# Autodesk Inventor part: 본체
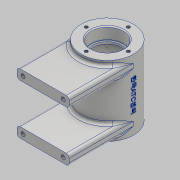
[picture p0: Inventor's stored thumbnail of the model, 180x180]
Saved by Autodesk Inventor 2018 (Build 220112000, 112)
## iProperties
Created: 2020-07
Part Number: 본체
Material: 알루미늄 6061
Document SubType Name: Modeling
Designer: home
Density: 2.7 g/cm^3
Appearance: 알루미늄 - 평지
Mass: 305.265 g
Surface Area: 357.573 cm^2
Volume: 113.061 cm^3
Author: home
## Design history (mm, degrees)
sketch "스케치1"
  geometry: L1 (0, 0)-(0, -55.603); L2 (26, 7.199)-(17, 7.199); L3 (16, 6.199)-(16, -4.501); L4 (15.7, -4.801)-(14, -4.801); L5 (14, -4.801)-(14, -6.801); L6 (14, -6.801)-(18, -6.801); L7 (21, -9.801)-(21, -45.801); L8 (18, -48.801)-(14, -48.801); L9 (14, -48.801)-(14, -50.801); L10 (14, -50.801)-(15.7, -50.801); L11 (16, -51.101)-(16, -61.801); L12 (17, -62.801)-(26, -62.801); L13 (26, -62.801)-(26, 7.199); L14 (16, 6.199)-(17, 7.199); L15 (16, -61.801)-(17, -62.801); A1 r 0.3 centre (15.7, -4.501) between (15.7, -4.801) and (16, -4.501); A2 r 0.3 centre (15.7, -51.101) between (16, -51.101) and (15.7, -50.801); A3 r 3 centre (18, -45.801) between (18, -48.801) and (21, -45.801); A4 r 3 centre (18, -9.801) between (21, -9.801) and (18, -6.801); 8 further points
  constraints: 30 end point, 16 point on line, 9 perpendicular, 8 point on circle, 8 tangent, 4 centre point, 2 equal radius, 2 midpoint, 1 horizontal, 1 horizontal alignment, 1 vertical
  dimensions: "d0" = 32 diameter of L3 L1; "d1" = 28 diameter of L5 L1; "d3" = 52 diameter of L13 L1; "d5" = 12 distance of point (16, 7.199) point (16, -4.801); "d6" = 12 distance of point (16, -50.801) point (16, -62.801); "d7" = 2 distance of L4.end L5.end; "d8" = 2 distance of L8.end L9.end; "d10" = 42 distance of point (21, -6.801) point (21, -48.801); "d11" = 42 diameter of L7 L1; "d12" = 7.19866 distance from line of L1.start L2; "d13" = 0.3 radius of A1; "d14" = 3 radius of A3; "d15" = 1 distance of L3.start point (16, 7.199); "d16" = 45 deg angle of L3 L14; "d17" = 1 distance of L11.end point (16, -62.801) (= d15); "d18" = 45 deg angle of L11 L15 (= d16)
revolve "회전1" sketch "스케치1" stored, may be unused: angle "d19" = 90 deg
sketch "스케치2"
  geometry: 1 further point
node "작업 평면1"
sketch "스케치3"
  geometry: L1 (-26, 7.199)-(26, 7.199) reference; C1 r 5 at (0, -27.801); 1 further point
  constraints: 1 centre point
  dimensions: "d21" = 10 diameter of C1; "d22" = 35 distance from line of L1 C1.centre; "d23" = 26 horizontal distance of L1.start C1.centre
extrude "돌출1" join sketch "스케치3" stored distance "d24" = 10; taper "d25" = 0 deg; dims "d0" = 32, "d1" = 28, "d3" = 52, "d5" = 12, "d6" = 12, "d7" = 2, "d8" = 2, "d10" = 42, "d11" = 42, "d12" = 7.19866, "d13" = 0.3, "d14" = 3, "d15" = 1, "d16" = 45 deg, "d17" = 1 (= d15), "d18" = 45 deg (= d16)
node "작업 평면3"
  node "작업 평면2"
sketch "스케치4"
  geometry: L1 (26, 0)-(26, -64); L2 (26, -64)-(-26, -64); L3 (-26, -64)-(-26, 0); A1 r 26 centre (0, 0) between (26, 0) and (-26, 0) reference; 1 further point
  constraints: 6 end point, 2 perpendicular, 2 point on circle, 1 tangent, 1 vertical
  dimensions: "d27" = 52 distance of L1.end L2.end; "d28" = 64 distance of L1.start L1.end
extrude "돌출2" join sketch "스케치4" distance "d29" = 10; taper "d30" = 0 deg
node "작업 평면4"
sketch "스케치5"
  geometry: L1 (0, 0)-(9.919, -27.251); L2 (0, 0)-(0, -45.606); 1 further point
  constraints: 4 end point, 1 coincident, 1 vertical
  dimensions: "d31" = 20 deg angle of L2 L1; "d32" = 29 distance of L1.start L1.end; "d33" = 15.59812 distance from line of L2.end L1
node "작업 평면5"
sketch "스케치7"
  geometry: C1 r 26 at (0, 0) reference; 2 further points
  constraints: 1 vertical alignment
  dimensions: "d38" = 21 distance of point (0, 21) point (0, 0)
hole "구멍1" sketch "스케치7" at (0, 21) diameter "d39" = 3.242; stored, may be unused: countersink angle "d43" = 90 deg, drill point angle "d45" = 118 deg; dims "d40" = 8, "d41" = 4, "d42" = 2, "d44" = 10
sketch "스케치8"
  geometry: C1 r 5 at (0, 0) reference; 2 further points
  constraints: 1 coincident
hole "구멍2" sketch "스케치8" at (0, 0) diameter "d49" = 5.188; stored, may be unused: countersink angle "d53" = 90 deg, drill point angle "d55" = 0 deg; dims "d50" = 12, "d51" = 4, "d52" = 2, "d54" = 16
sketch "스케치10"
  geometry: L1 (0, 10)-(52, 10) reference; L2 (0, -50)-(52, -50) reference; 5 further points
  constraints: 2 horizontal alignment, 2 vertical alignment
  dimensions: "d63" = 5 distance from line of L1 point (46, 5); "d64" = 40 distance of point (6, 5) point (46, 5); "d65" = 20 horizontal distance of point (26, 7.801) point (46, 5); "d66" = 5 distance from line of L2 point (46, -45)
hole "구멍4" sketch "스케치10" at (46, 5), (46, -45), (6, -45), (6, 5) diameter "d67" = 4.134; stored, may be unused: countersink angle "d71" = 90 deg, drill point angle "d73" = 118 deg; dims "d68" = 8, "d69" = 4, "d70" = 2, "d72" = 10
fillet "모깎기1" dims "d74" = 3
fillet "모깎기2" dims "d75" = 3, "d76" = 2
node "작업 평면6"
sketch "스케치11"
  geometry: L1 (-26, 7.199)-(26, 7.199) reference; L2 (26, 7.199)-(26, -62.801) reference; 2 further points
  constraints: 1 other
  dimensions: "d78" = 35 distance from line of L1 point (0, -27.801); "d79" = 26 distance from line of L2 point (0, -27.801)
feature "엠보싱1" sketch "스케치11" dims "d80" = 0.5, "d81" = 0
node "작업 평면7"
sketch "스케치12"
  geometry: L1 (0, 0)-(-9.919, -27.251); L2 (0, 0)-(0, -49.376); 1 further point
  constraints: 4 end point, 1 coincident, 1 vertical
  dimensions: "d82" = 20 deg angle of L2 L1; "d83" = 29 distance of L1.start L1.end; "d84" = 16.88773 distance from line of L2.end L1
node "작업 평면9"
sketch "스케치14"
  geometry: L1 (24.432, -27)-(46.321, -27) reference; C1 r 6 at (0, 0); 1 further point
  constraints: 1 centre point
  dimensions: "d85" = 12 diameter of C1; "d86" = 27.80134 distance of point (0, 27.801) C1.centre; "d87" = 27 distance from line of L1 C1.centre
extrude "돌출4" join sketch "스케치14" stored distance "d88" = 10; taper "d89" = 0 deg
sketch "스케치15"
  geometry: C1 r 6 at (0, 0) reference; 2 further points
  constraints: 1 coincident
hole "구멍5" sketch "스케치15" at (0, 0) diameter "d90" = 5.188; stored, may be unused: countersink angle "d94" = 90 deg, drill point angle "d96" = 0 deg; dims "d91" = 12, "d92" = 4, "d93" = 2, "d95" = 16
fillet "모깎기3" dims "d97" = 2
node "솔리드1"
mirror "미러1"
pattern_circular "원형 패턴1" dims angle "d47" = 360 deg
mirror "미러2"
node "투영된 루프2"
other parameters: "d20" = 29, "d77" = 48
